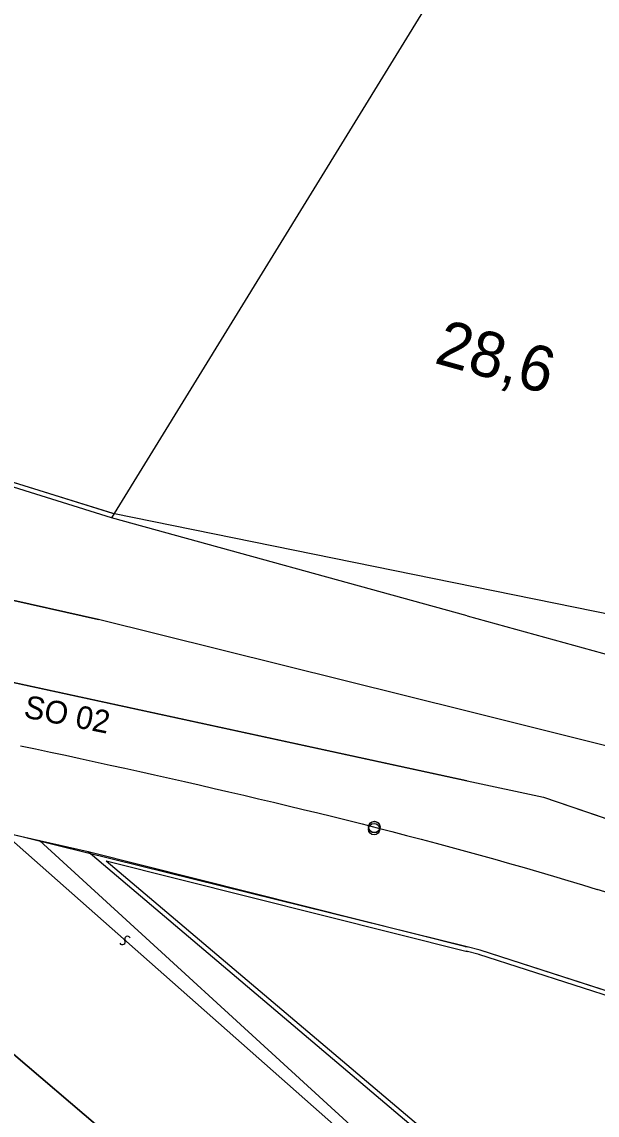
# Model space of a CAD drawing. Extents: x -792659 to -786947, y -1118170 to -1109641.
# Drawn here: x -789591.6 to -789553.7, y -1114317.5 to -1114245.3 of the extents above; entities that cross this region are included whole.
import ezdxf

# ---------------------------------------------------------------- set-up
doc = ezdxf.new("R2010")
doc.units = 0
doc.layers.add('1', color=7, linetype='Continuous')

msp = doc.modelspace()

# ---------------------------------------------------------------- linework, layer by layer
at = {"layer": '1'}
for p, q in [((-789562.235, -1114239.835), (-789585.72, -1114278.05)), ((-789585.63, -1114277.763), (-789626.15, -1114265.153)), ((-789585.72, -1114278.05), (-789626.24, -1114265.44)), ((-789562.235, -1114284.536), (-789585.72, -1114278.05)), ((-789586.59, -1114284.77), (-789609.87, -1114279.55)), ((-789609.87, -1114279.55), (-789586.59, -1114284.77)), ((-789562.235, -1114284.536), (-789475.21, -1114308.57)), ((-789562.235, -1114290.833), (-789586.59, -1114284.77)), ((-789603.91, -1114286.39), (-789562.235, -1114295.417)), ((-789603.91, -1114286.39), (-789562.26, -1114295.41)), ((-789562.235, -1114339.028), (-789619.3, -1114290.36)), ((-789619.3, -1114290.36), (-789562.235, -1114339.028)), ((-789548.79, -1114294.18), (-789562.235, -1114290.833)), ((-789562.235, -1114295.417), (-789557.19, -1114296.51)), ((-789557.19, -1114296.51), (-789534.19, -1114304.37)), ((-789592.9, -1114298.82), (-789562.235, -1114325.922)), ((-789592.9, -1114298.82), (-789590.47, -1114299.37)), ((-789590.47, -1114299.37), (-789563.4, -1114324.15)), ((-789590.47, -1114299.37), (-789587.26, -1114300.1)), ((-789587.26, -1114300.1), (-789562.096, -1114321.394)), ((-789587.26, -1114300.1), (-789562.235, -1114306.385)), ((-789586.079, -1114300.705), (-789562.235, -1114306.694)), ((-789586.079, -1114300.705), (-789562.235, -1114320.883)), ((-789562.362, -1114306.353), (-789562.235, -1114306.353)), ((-789561.453, -1114306.891), (-789562.308, -1114306.676)), ((-789561.38, -1114306.6), (-789562.235, -1114306.385)), ((-789534.272, -1114315.665), (-789561.472, -1114306.885)), ((-789534.18, -1114315.38), (-789561.38, -1114306.6))]:
    msp.add_line(p, q, dxfattribs=at)
for points in [[(-789674.01, -1114222.232), (-789653.09, -1114241.037), (-789626.089, -1114265.173), (-789585.645, -1114277.759), (-789547.205, -1114285.569), (-789509.71, -1114297.224), (-789475.119, -1114308.284), (-789456.079, -1114314.364), (-789451.572, -1114315.806)], [(-789534.18, -1114315.38), (-789561.38, -1114306.6), (-789562.235, -1114306.385), (-789592.9, -1114298.82), (-789600.46, -1114294.39), (-789619.3, -1114290.36), (-789624.34, -1114291.37), (-789641.23, -1114287.32), (-789672.68, -1114277.31), (-789724.61, -1114250.58), (-789729.37, -1114244.66), (-789729.37, -1114234.086), (-789721.98, -1114237.82), (-789717.72, -1114240.35), (-789691.28, -1114256.01), (-789665.23, -1114268.84), (-789640.19, -1114272.7), (-789627.07, -1114282.33), (-789607.19, -1114286.63), (-789603.91, -1114286.39), (-789562.235, -1114295.417), (-789557.19, -1114296.51), (-789534.19, -1114304.37)], [(-789591.726, -1114293.103), (-789590.742, -1114293.314), (-789589.758, -1114293.526), (-789588.774, -1114293.738), (-789587.791, -1114293.951), (-789586.808, -1114294.166), (-789585.825, -1114294.381), (-789584.842, -1114294.597), (-789583.859, -1114294.814), (-789582.877, -1114295.033), (-789581.895, -1114295.253), (-789580.914, -1114295.475), (-789579.932, -1114295.698), (-789578.951, -1114295.922), (-789577.971, -1114296.148), (-789576.991, -1114296.377), (-789576.011, -1114296.606), (-789575.032, -1114296.838), (-789574.053, -1114297.072), (-789573.075, -1114297.308), (-789572.097, -1114297.546), (-789571.12, -1114297.787), (-789570.143, -1114298.029), (-789569.167, -1114298.274), (-789568.192, -1114298.522), (-789567.217, -1114298.772), (-789566.243, -1114299.025), (-789565.27, -1114299.281), (-789564.298, -1114299.54), (-789563.326, -1114299.801), (-789562.355, -1114300.066), (-789561.385, -1114300.333), (-789560.416, -1114300.604), (-789559.447, -1114300.878), (-789558.48, -1114301.155), (-789557.514, -1114301.436), (-789556.548, -1114301.72), (-789555.584, -1114302.007), (-789554.621, -1114302.299), (-789553.659, -1114302.594)], [(-789591.726, -1114293.103), (-789590.742, -1114293.314), (-789589.758, -1114293.526), (-789588.774, -1114293.738), (-789587.791, -1114293.951), (-789586.808, -1114294.166), (-789585.825, -1114294.381), (-789584.842, -1114294.597), (-789583.859, -1114294.814), (-789582.877, -1114295.033), (-789581.895, -1114295.253), (-789580.914, -1114295.475), (-789579.932, -1114295.698), (-789578.951, -1114295.922), (-789577.971, -1114296.148), (-789576.991, -1114296.377), (-789576.011, -1114296.606), (-789575.032, -1114296.838), (-789574.053, -1114297.072), (-789573.075, -1114297.308), (-789572.097, -1114297.546), (-789571.12, -1114297.787), (-789570.143, -1114298.029), (-789569.167, -1114298.274), (-789568.192, -1114298.522), (-789567.217, -1114298.772), (-789566.243, -1114299.025), (-789565.27, -1114299.281), (-789564.298, -1114299.54), (-789563.326, -1114299.801), (-789562.355, -1114300.066), (-789561.385, -1114300.333), (-789560.416, -1114300.604), (-789559.447, -1114300.878), (-789558.48, -1114301.155), (-789557.514, -1114301.436), (-789556.548, -1114301.72), (-789555.584, -1114302.007), (-789554.621, -1114302.299), (-789553.659, -1114302.594)], [(-789591.726, -1114293.103), (-789590.742, -1114293.314), (-789589.758, -1114293.526), (-789588.774, -1114293.738), (-789587.791, -1114293.951), (-789586.808, -1114294.166), (-789585.825, -1114294.381), (-789584.842, -1114294.597), (-789583.859, -1114294.814), (-789582.877, -1114295.033), (-789581.895, -1114295.253), (-789580.914, -1114295.475), (-789579.932, -1114295.698), (-789578.951, -1114295.922), (-789577.971, -1114296.148), (-789576.991, -1114296.377), (-789576.011, -1114296.606), (-789575.032, -1114296.838), (-789574.053, -1114297.072), (-789573.075, -1114297.308), (-789572.097, -1114297.546), (-789571.12, -1114297.787), (-789570.143, -1114298.029), (-789569.167, -1114298.274), (-789568.192, -1114298.522), (-789567.217, -1114298.772), (-789566.243, -1114299.025), (-789565.27, -1114299.281), (-789564.298, -1114299.54), (-789563.326, -1114299.801), (-789562.355, -1114300.066), (-789561.385, -1114300.333), (-789560.416, -1114300.604), (-789559.447, -1114300.878), (-789558.48, -1114301.155), (-789557.514, -1114301.436), (-789556.548, -1114301.72), (-789555.584, -1114302.007), (-789554.621, -1114302.299), (-789553.659, -1114302.594)], [(-789591.726, -1114293.103), (-789590.742, -1114293.314), (-789589.758, -1114293.526), (-789588.774, -1114293.738), (-789587.791, -1114293.951), (-789586.808, -1114294.166), (-789585.825, -1114294.381), (-789584.842, -1114294.597), (-789583.859, -1114294.814), (-789582.877, -1114295.033), (-789581.895, -1114295.253), (-789580.914, -1114295.475), (-789579.932, -1114295.698), (-789578.951, -1114295.922), (-789577.971, -1114296.148), (-789576.991, -1114296.377), (-789576.011, -1114296.606), (-789575.032, -1114296.838), (-789574.053, -1114297.072), (-789573.075, -1114297.308), (-789572.097, -1114297.546), (-789571.12, -1114297.787), (-789570.143, -1114298.029), (-789569.167, -1114298.274), (-789568.192, -1114298.522), (-789567.217, -1114298.772), (-789566.243, -1114299.025), (-789565.27, -1114299.281), (-789564.298, -1114299.54), (-789563.326, -1114299.801), (-789562.355, -1114300.066), (-789561.385, -1114300.333), (-789560.416, -1114300.604), (-789559.447, -1114300.878), (-789558.48, -1114301.155), (-789557.514, -1114301.436), (-789556.548, -1114301.72), (-789555.584, -1114302.007), (-789554.621, -1114302.299), (-789553.659, -1114302.594)]]:
    msp.add_lwpolyline(points, dxfattribs=at)
for centre in [(-789568.39, -1114298.62), (-789568.39, -1114298.62), (-789568.37, -1114298.47), (-789568.37, -1114298.48)]:
    msp.add_circle(centre, 0.375, dxfattribs=at)
for centre, radius, start, end in [((-789628.904, -1114546.239), 255, 50.01412, 72.83771), ((-789628.904, -1114546.239), 255, 50.01412, 72.83771), ((-789585.002, -1114306.054), 0.188, 207.58203, 27.58203), ((-789584.669, -1114305.88), 0.188, 27.58203, 207.58202)]:
    msp.add_arc(centre, radius, start, end, dxfattribs=at)

# ---------------------------------------------------------------- texts
for s, height, rotation, p in [('28,6', 3, 344.5069, (-789564.49, -1114267.81)), ('SO 02', 1.5, 348.90896, (-789591.58, -1114291.22))]:
    msp.add_text(s, height=height, rotation=rotation, dxfattribs=at).set_placement(p)

doc.saveas('drawing.dxf')
